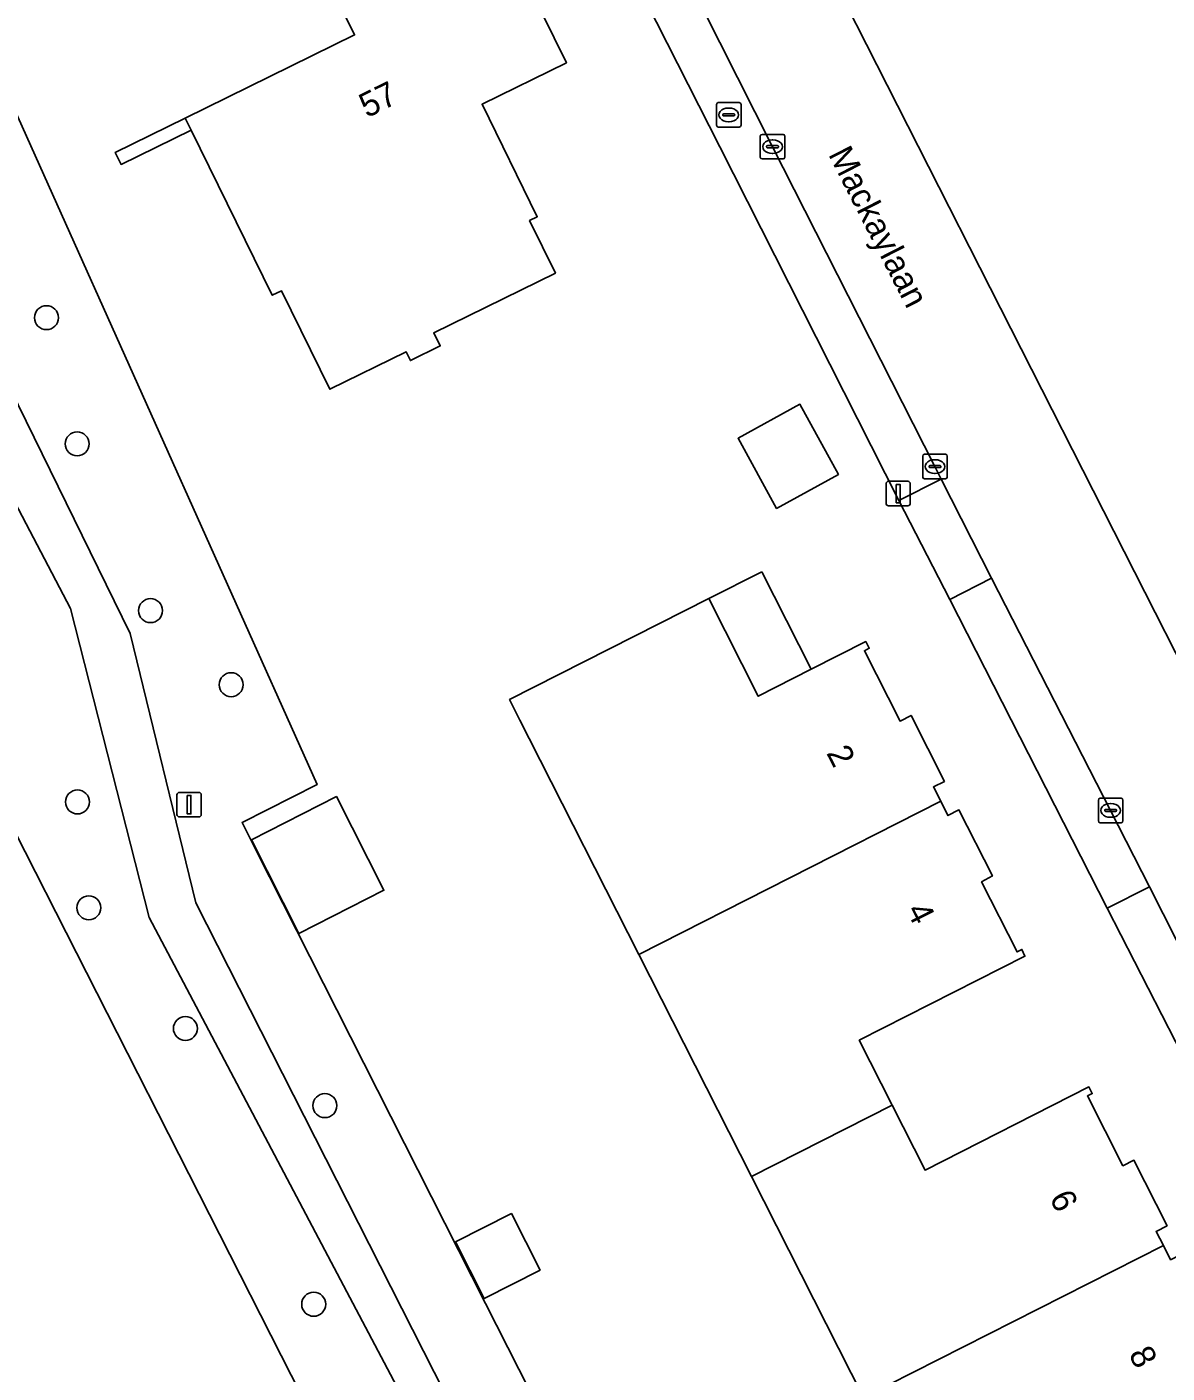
# Model space of a CAD drawing. Extents: x 162722 to 165104, y 384719 to 386284.
# Drawn here: x 163761.5 to 163808, y 385115.6 to 385170.5 of the extents above; entities that cross this region are included whole.
import ezdxf

# ---------------------------------------------------------------- set-up
doc = ezdxf.new("R2010")
doc.units = 0
for name, color, linetype in [('IMGEO_Boom', 7, 'Continuous'), ('IMGEO_Brandkraan', 7, 'Continuous'), ('IMGEO_Erf', 7, 'Continuous'), ('IMGEO_Groenvoorziening', 7, 'Continuous'), ('IMGEO_Kolk', 7, 'Continuous'), ('IMGEO_Lichtmast', 7, 'Continuous'), ('IMGEO_Muur', 7, 'Continuous'), ('IMGEO_Openbare_ruimte_label', 7, 'Continuous'), ('IMGEO_Pand', 7, 'Continuous'), ('IMGEO_Pand_nummerreeks', 7, 'Continuous'), ('IMGEO_Pand_overbouw', 7, 'Continuous'), ('IMGEO_Rijbaan_lokaal_open', 7, 'Continuous'), ('IMGEO_Voetpad_open', 7, 'Continuous')]:
    doc.layers.add(name, color=color, linetype=linetype)

msp = doc.modelspace()

# ---------------------------------------------------------------- linework, layer by layer
at = {"layer": 'IMGEO_Boom'}
for centre in [(163762.273, 385158.667), (163763.528, 385153.517), (163766.522, 385146.715), (163769.809, 385143.694), (163763.538, 385138.91), (163764.003, 385134.594), (163767.942, 385129.668), (163773.631, 385126.52), (163773.175, 385118.417)]:
    msp.add_circle(centre, 0.489, dxfattribs=at)
at = {"layer": 'IMGEO_Brandkraan'}
for p, q in [((163789.606, 385166.514), (163789.606, 385167.366)), ((163789.681, 385167.44), (163790.533, 385167.44)), ((163790.094, 385167.22), (163790.119, 385167.22)), ((163790.607, 385167.366), (163790.607, 385166.514)), ((163789.865, 385166.934), (163789.865, 385166.946)), ((163790.303, 385166.897), (163789.905, 385166.897)), ((163789.908, 385166.983), (163790.306, 385166.983)), ((163790.117, 385166.66), (163790.092, 385166.66)), ((163790.349, 385166.946), (163790.349, 385166.934)), ((163790.533, 385166.44), (163789.681, 385166.44))]:
    msp.add_line(p, q, dxfattribs=at)
for points in [[(163789.606, 385166.514), (163789.606, 385167.366)], [(163789.681, 385167.44), (163790.533, 385167.44)], [(163790.607, 385167.366), (163790.607, 385166.514)], [(163790.533, 385166.44), (163789.681, 385166.44)]]:
    msp.add_lwpolyline(points, dxfattribs=at)
for centre, radius, start, end in [((163789.683, 385167.364), 0.0765, 91.552, 178.448), ((163789.683, 385167.364), 0.0765, 91.552, 178.448), ((163790.531, 385167.364), 0.0765, 1.552, 88.448), ((163790.531, 385167.364), 0.0765, 1.552, 88.448), ((163789.683, 385166.516), 0.0765, 181.552, 268.448), ((163789.683, 385166.516), 0.0765, 181.552, 268.448), ((163789.905, 385166.943), 0.0403, 85.8775, 175.7526), ((163789.902, 385166.933), 0.0366, 178.938, 274.7102), ((163790.306, 385166.94), 0.043, 264.8664, 352.4533), ((163790.31, 385166.945), 0.0386, 1.7309, 96.639), ((163790.531, 385166.516), 0.0765, 271.552, 358.448), ((163790.531, 385166.516), 0.0765, 271.552, 358.448)]:
    msp.add_arc(centre, radius, start, end, dxfattribs=at)
for centre, major_axis, ratio, start_param, end_param in [((163790.093, 385166.94), (-0.387, 0.002), 0.722429, 4.712389, 7.853982), ((163790.118, 385166.94), (-0.39, 0.002), 0.717154, 1.570796, 4.712389)]:
    msp.add_ellipse(centre, major_axis=major_axis, ratio=ratio, start_param=start_param, end_param=end_param, dxfattribs=at)
at = {"layer": 'IMGEO_Erf'}
for points in [[(163789.008, 385183.038), (163818.416, 385125.146), (163829.972, 385102.357), (163838.425, 385085.655)], [(163777.061, 385181.644), (163776.532, 385181.386), (163770.303, 385178.196), (163758.67, 385172.275), (163773.324, 385139.627), (163770.253, 385138.072), (163770.819, 385136.953), (163780.19, 385118.446), (163789.688, 385099.725), (163809.284, 385061.102), (163812.187, 385062.627), (163827.853, 385070.567), (163835.892, 385074.67), (163835.122, 385076.225), (163833.369, 385079.662), (163826.65, 385092.98), (163823.907, 385098.369), (163817.57, 385111.145), (163814.72, 385116.503), (163808.329, 385129.137), (163805.546, 385134.581), (163799.125, 385147.174), (163797.047, 385151.214), (163789.743, 385165.63)], [(163789.743, 385165.63), (163782.429, 385180.056)], [(163720.799, 385149.656), (163733.386, 385124.897), (163735.22, 385121.265), (163741.754, 385108.434), (163745.114, 385101.827), (163751.491, 385089.235), (163753.386, 385085.536), (163753.931, 385084.458), (163761.818, 385088.577), (163781.027, 385098.268), (163760.145, 385139.341), (163746.528, 385166.095)], [(163795.605, 385114.608), (163791.032, 385123.624), (163786.435, 385132.69), (163781.966, 385141.503), (163781.586, 385142.251), (163781.163, 385143.084), (163789.289, 385147.205), (163791.308, 385143.224), (163793.474, 385144.323), (163795.698, 385145.451), (163795.835, 385145.182), (163795.637, 385145.081), (163797.093, 385142.212), (163797.542, 385142.44), (163798.906, 385139.749), (163798.457, 385139.521), (163798.753, 385138.939), (163799.049, 385138.355), (163799.498, 385138.583), (163800.862, 385135.892), (163800.42, 385135.65), (163801.869, 385132.795), (163802.067, 385132.896), (163802.185, 385132.616), (163795.431, 385129.191), (163796.775, 385126.542), (163798.118, 385123.893), (163804.799, 385127.282), (163804.935, 385127.015), (163804.739, 385126.915), (163806.185, 385124.065), (163806.631, 385124.291), (163807.986, 385121.618), (163807.54, 385121.392), (163807.834, 385120.811), (163808.127, 385120.234)]]:
    msp.add_lwpolyline(points, dxfattribs=at)
for points in [[(163777.118, 385156.918), (163776.943, 385157.274), (163773.834, 385155.746), (163771.858, 385159.767), (163771.482, 385159.582), (163768.172, 385166.319), (163765.319, 385164.917), (163765.078, 385165.407), (163767.931, 385166.809), (163774.843, 385170.205), (163773.498, 385172.942), (163780.009, 385176.141), (163783.486, 385169.066), (163780.042, 385167.374), (163782.296, 385162.787), (163781.979, 385162.631), (163783.033, 385160.485), (163778.075, 385158.049), (163778.337, 385157.517)], [(163790.484, 385153.749), (163793.007, 385155.137), (163794.583, 385152.271), (163792.06, 385150.883)], [(163770.632, 385137.371), (163774.103, 385139.131), (163776.043, 385135.306), (163772.572, 385133.546)], [(163778.955, 385120.962), (163781.238, 385122.12), (163782.409, 385119.809), (163780.126, 385118.652)]]:
    msp.add_lwpolyline(points, close=True, dxfattribs=at)
at = {"layer": 'IMGEO_Groenvoorziening'}
for points in [[(163770.819, 385136.953), (163770.253, 385138.072), (163773.324, 385139.627), (163758.67, 385172.275), (163753.89, 385169.842), (163754.236, 385169.136), (163765.683, 385145.787), (163768.37, 385134.799), (163785.613, 385100.832), (163787.475, 385098.737), (163789.688, 385099.725), (163780.19, 385118.446)], [(163751.75, 385168.753), (163746.528, 385166.095), (163760.145, 385139.341), (163781.027, 385098.268), (163761.818, 385088.577), (163753.931, 385084.458), (163756.413, 385079.553), (163766.533, 385084.8), (163769.171, 385086.138), (163773.434, 385088.46), (163776.32, 385089.774), (163779.555, 385090.879), (163782.967, 385093.011), (163784.312, 385093.815), (163784.3, 385096.739), (163783.48, 385101.975), (163766.464, 385134.202), (163763.257, 385146.803)]]:
    msp.add_lwpolyline(points, close=True, dxfattribs=at)
for points in [[(163751.75, 385168.753), (163763.257, 385146.803), (163766.464, 385134.202), (163783.48, 385101.975)], [(163785.613, 385100.832), (163768.37, 385134.799), (163765.683, 385145.787), (163754.236, 385169.136)]]:
    msp.add_lwpolyline(points, dxfattribs=at)
at = {"layer": 'IMGEO_Kolk'}
for p, q in [((163791.393, 385165.216), (163791.393, 385166.068)), ((163791.468, 385166.142), (163792.32, 385166.142)), ((163792.394, 385166.068), (163792.394, 385165.216)), ((163791.652, 385165.636), (163791.652, 385165.648)), ((163792.09, 385165.599), (163791.692, 385165.599)), ((163791.695, 385165.685), (163792.093, 385165.685)), ((163791.881, 385165.922), (163791.906, 385165.922)), ((163792.136, 385165.648), (163792.136, 385165.636)), ((163792.32, 385165.142), (163791.468, 385165.142)), ((163791.904, 385165.362), (163791.879, 385165.362)), ((163798.018, 385152.166), (163798.018, 385153.018)), ((163798.093, 385153.092), (163798.945, 385153.092)), ((163798.506, 385152.872), (163798.531, 385152.872)), ((163799.019, 385153.018), (163799.019, 385152.166)), ((163798.277, 385152.586), (163798.277, 385152.598)), ((163798.715, 385152.549), (163798.317, 385152.549)), ((163798.32, 385152.635), (163798.718, 385152.635)), ((163798.529, 385152.312), (163798.504, 385152.312)), ((163798.761, 385152.598), (163798.761, 385152.586)), ((163798.945, 385152.092), (163798.093, 385152.092)), ((163805.259, 385139.063), (163806.111, 385139.063)), ((163805.184, 385138.137), (163805.184, 385138.989)), ((163805.443, 385138.557), (163805.443, 385138.569)), ((163805.881, 385138.52), (163805.483, 385138.52)), ((163805.486, 385138.606), (163805.884, 385138.606)), ((163805.672, 385138.843), (163805.697, 385138.843)), ((163805.927, 385138.569), (163805.927, 385138.557)), ((163806.185, 385138.989), (163806.185, 385138.137)), ((163806.111, 385138.063), (163805.259, 385138.063)), ((163805.695, 385138.283), (163805.67, 385138.283))]:
    msp.add_line(p, q, dxfattribs=at)
for points in [[(163791.393, 385165.216), (163791.393, 385166.068)], [(163791.468, 385166.142), (163792.32, 385166.142)], [(163792.394, 385166.068), (163792.394, 385165.216)], [(163792.32, 385165.142), (163791.468, 385165.142)], [(163798.018, 385152.166), (163798.018, 385153.018)], [(163798.093, 385153.092), (163798.945, 385153.092)], [(163799.019, 385153.018), (163799.019, 385152.166)], [(163798.945, 385152.092), (163798.093, 385152.092)], [(163805.259, 385139.063), (163806.111, 385139.063)], [(163805.184, 385138.137), (163805.184, 385138.989)], [(163806.185, 385138.989), (163806.185, 385138.137)], [(163806.111, 385138.063), (163805.259, 385138.063)]]:
    msp.add_lwpolyline(points, dxfattribs=at)
for centre, radius, start, end in [((163791.47, 385166.066), 0.0765, 91.552, 178.448), ((163791.47, 385166.066), 0.0765, 91.552, 178.448), ((163792.318, 385166.066), 0.0765, 1.552, 88.448), ((163792.318, 385166.066), 0.0765, 1.552, 88.448), ((163791.692, 385165.645), 0.0403, 85.8775, 175.7526), ((163791.689, 385165.635), 0.0366, 178.938, 274.7102), ((163792.093, 385165.642), 0.043, 264.8664, 352.4533), ((163792.097, 385165.647), 0.0386, 1.7309, 96.639), ((163791.47, 385165.218), 0.0765, 181.552, 268.448), ((163791.47, 385165.218), 0.0765, 181.552, 268.448), ((163792.318, 385165.218), 0.0765, 271.552, 358.448), ((163792.318, 385165.218), 0.0765, 271.552, 358.448), ((163798.095, 385153.016), 0.0765, 91.552, 178.448), ((163798.095, 385153.016), 0.0765, 91.552, 178.448), ((163798.943, 385153.016), 0.0765, 1.552, 88.448), ((163798.943, 385153.016), 0.0765, 1.552, 88.448), ((163798.317, 385152.595), 0.0403, 85.8775, 175.7526), ((163798.314, 385152.585), 0.0366, 178.938, 274.7102), ((163798.718, 385152.592), 0.043, 264.8664, 352.4533), ((163798.722, 385152.597), 0.0386, 1.7309, 96.639), ((163798.095, 385152.168), 0.0765, 181.552, 268.448), ((163798.095, 385152.168), 0.0765, 181.552, 268.448), ((163798.943, 385152.168), 0.0765, 271.552, 358.448), ((163798.943, 385152.168), 0.0765, 271.552, 358.448), ((163805.261, 385138.987), 0.0765, 91.552, 178.448), ((163805.261, 385138.987), 0.0765, 91.552, 178.448), ((163806.109, 385138.987), 0.0765, 1.552, 88.448), ((163806.109, 385138.987), 0.0765, 1.552, 88.448), ((163805.483, 385138.566), 0.0403, 85.8775, 175.7526), ((163805.48, 385138.556), 0.0366, 178.938, 274.7102), ((163805.884, 385138.563), 0.043, 264.8664, 352.4533), ((163805.888, 385138.568), 0.0386, 1.7309, 96.639), ((163805.261, 385138.139), 0.0765, 181.552, 268.448), ((163805.261, 385138.139), 0.0765, 181.552, 268.448), ((163806.109, 385138.139), 0.0765, 271.552, 358.448), ((163806.109, 385138.139), 0.0765, 271.552, 358.448)]:
    msp.add_arc(centre, radius, start, end, dxfattribs=at)
for centre, major_axis, ratio, start_param, end_param in [((163791.88, 385165.642), (-0.387, 0.002), 0.722429, 4.712389, 7.853982), ((163791.905, 385165.642), (-0.39, 0.002), 0.717154, 1.570796, 4.712389), ((163798.505, 385152.592), (-0.387, 0.002), 0.722429, 4.712389, 7.853982), ((163798.53, 385152.592), (-0.39, 0.002), 0.717154, 1.570796, 4.712389), ((163805.671, 385138.563), (-0.387, 0.002), 0.722429, 4.712389, 7.853982), ((163805.696, 385138.563), (-0.39, 0.002), 0.717154, 1.570796, 4.712389)]:
    msp.add_ellipse(centre, major_axis=major_axis, ratio=ratio, start_param=start_param, end_param=end_param, dxfattribs=at)
at = {"layer": 'IMGEO_Lichtmast'}
for p, q in [((163796.522, 385151.091), (163796.522, 385151.891)), ((163796.522, 385151.891), (163796.522, 385151.091)), ((163796.622, 385151.991), (163797.412, 385151.991)), ((163797.412, 385151.991), (163796.622, 385151.991)), ((163797.512, 385151.891), (163797.512, 385151.091)), ((163797.512, 385151.091), (163797.512, 385151.891)), ((163797.412, 385150.991), (163796.622, 385150.991)), ((163796.622, 385150.991), (163797.412, 385150.991)), ((163767.598, 385138.4), (163767.598, 385139.2)), ((163767.598, 385139.2), (163767.598, 385138.4)), ((163767.698, 385139.3), (163768.488, 385139.3)), ((163768.488, 385139.3), (163767.698, 385139.3)), ((163768.588, 385139.2), (163768.588, 385138.4)), ((163768.588, 385138.4), (163768.588, 385139.2)), ((163768.488, 385138.3), (163767.698, 385138.3)), ((163767.698, 385138.3), (163768.488, 385138.3))]:
    msp.add_line(p, q, dxfattribs=at)
for points in [[(163796.942, 385151.866), (163797.092, 385151.866), (163797.092, 385151.116), (163796.942, 385151.116), (163796.942, 385151.866)], [(163768.018, 385139.175), (163768.168, 385139.175), (163768.168, 385138.425), (163768.018, 385138.425), (163768.018, 385139.175)]]:
    msp.add_lwpolyline(points, dxfattribs=at)
for centre, start, end in [((163796.622, 385151.891), 90, 180), ((163796.622, 385151.891), 90, 180), ((163797.412, 385151.891), 0, 90), ((163797.412, 385151.891), 360, 90), ((163796.622, 385151.091), 180, 270), ((163796.622, 385151.091), 180, 270), ((163797.412, 385151.091), 270, 0), ((163797.412, 385151.091), 270, 0), ((163767.698, 385139.2), 90, 180), ((163767.698, 385139.2), 90, 180), ((163768.488, 385139.2), 0, 90), ((163768.488, 385139.2), 360, 90), ((163767.698, 385138.4), 180, 270), ((163767.698, 385138.4), 180, 270), ((163768.488, 385138.4), 270, 0), ((163768.488, 385138.4), 270, 0)]:
    msp.add_arc(centre, 0.1, start, end, dxfattribs=at)
at = {"layer": 'IMGEO_Muur'}
msp.add_lwpolyline([(163768.172, 385166.319), (163767.931, 385166.809), (163765.078, 385165.407), (163765.319, 385164.917)], close=True, dxfattribs=at)
at = {"layer": 'IMGEO_Pand'}
for points in [[(163776.943, 385157.274), (163777.118, 385156.918), (163778.337, 385157.517), (163778.075, 385158.049), (163783.033, 385160.485), (163781.979, 385162.631), (163782.296, 385162.787), (163780.042, 385167.374), (163783.486, 385169.066), (163780.009, 385176.141), (163773.498, 385172.942), (163774.843, 385170.205), (163767.931, 385166.809), (163768.172, 385166.319), (163771.482, 385159.582), (163771.858, 385159.767), (163773.834, 385155.746)], [(163794.583, 385152.271), (163793.007, 385155.137), (163790.484, 385153.749), (163792.06, 385150.883)], [(163789.289, 385147.205), (163781.163, 385143.084), (163781.586, 385142.251), (163781.966, 385141.503), (163786.435, 385132.69), (163798.753, 385138.939), (163798.457, 385139.521), (163798.906, 385139.749), (163797.542, 385142.44), (163797.093, 385142.212), (163795.637, 385145.081), (163795.835, 385145.182), (163795.698, 385145.451), (163793.474, 385144.323), (163791.308, 385143.224)], [(163770.632, 385137.371), (163772.572, 385133.546), (163776.043, 385135.306), (163774.103, 385139.131)], [(163796.775, 385126.542), (163795.431, 385129.191), (163802.185, 385132.616), (163802.067, 385132.896), (163801.869, 385132.795), (163800.42, 385135.65), (163800.862, 385135.892), (163799.498, 385138.583), (163799.049, 385138.355), (163798.753, 385138.939), (163786.435, 385132.69), (163791.032, 385123.624)], [(163807.834, 385120.811), (163807.54, 385121.392), (163807.986, 385121.618), (163806.631, 385124.291), (163806.185, 385124.065), (163804.739, 385126.915), (163804.935, 385127.015), (163804.799, 385127.282), (163798.118, 385123.893), (163796.775, 385126.542), (163791.032, 385123.624), (163795.605, 385114.608)], [(163778.955, 385120.962), (163780.126, 385118.652), (163782.409, 385119.809), (163781.238, 385122.12)], [(163804.584, 385111.158), (163809.431, 385113.617), (163811.259, 385114.544), (163811.124, 385114.812), (163810.928, 385114.712), (163809.482, 385117.562), (163809.928, 385117.788), (163808.573, 385120.46), (163808.127, 385120.234), (163807.834, 385120.811), (163795.605, 385114.608), (163800.201, 385105.546), (163805.952, 385108.461)]]:
    msp.add_lwpolyline(points, close=True, dxfattribs=at)
at = {"layer": 'IMGEO_Pand_overbouw'}
msp.add_lwpolyline([(163791.455, 385148.303), (163789.289, 385147.205), (163791.308, 385143.224), (163793.474, 385144.323)], close=True, dxfattribs=at)
at = {"layer": 'IMGEO_Rijbaan_lokaal_open'}
for points in [[(163838.425, 385085.655), (163829.972, 385102.357), (163818.416, 385125.146), (163789.008, 385183.038)], [(163784.431, 385180.42), (163785.452, 385178.417), (163791.894, 385165.642), (163798.519, 385152.592), (163798.773, 385152.083), (163800.827, 385148.034), (163805.685, 385138.563), (163807.264, 385135.445), (163810.036, 385129.99), (163816.441, 385117.378), (163818.893, 385112.55), (163819.19, 385111.977), (163825.15, 385100.233), (163825.636, 385099.228), (163828.368, 385093.833), (163832.544, 385085.598), (163835.093, 385080.507), (163835.473, 385079.771)]]:
    msp.add_lwpolyline(points, dxfattribs=at)
at = {"layer": 'IMGEO_Voetpad_open'}
msp.add_lwpolyline([(163782.429, 385180.056), (163789.743, 385165.63), (163797.047, 385151.214), (163798.773, 385152.083), (163798.519, 385152.592), (163791.894, 385165.642), (163785.452, 385178.417), (163784.431, 385180.42)], dxfattribs=at)
for points in [[(163798.773, 385152.083), (163797.047, 385151.214), (163799.125, 385147.174), (163800.827, 385148.034)], [(163800.827, 385148.034), (163799.125, 385147.174), (163805.546, 385134.581), (163807.264, 385135.445), (163805.685, 385138.563)], [(163810.036, 385129.99), (163807.264, 385135.445), (163805.546, 385134.581), (163808.329, 385129.137)]]:
    msp.add_lwpolyline(points, close=True, dxfattribs=at)

# ---------------------------------------------------------------- texts
at = {"layer": 'IMGEO_Openbare_ruimte_label'}
msp.add_text('Mackaylaan', height=1, rotation=297.0778, dxfattribs=at).set_placement((163794.151, 385165.333))
at = {"layer": 'IMGEO_Pand_nummerreeks'}
for s, rotation, p in [('57', 26.167, (163775.348, 385166.799)), ('2', 296.8944, (163794.075, 385140.908)), ('4', 296.8967, (163797.33, 385134.493)), ('6', 296.8913, (163803.169, 385122.758)), ('8', 296.895, (163806.402, 385116.386))]:
    msp.add_text(s, height=1, rotation=rotation, dxfattribs=at).set_placement(p)

doc.saveas('drawing.dxf')
